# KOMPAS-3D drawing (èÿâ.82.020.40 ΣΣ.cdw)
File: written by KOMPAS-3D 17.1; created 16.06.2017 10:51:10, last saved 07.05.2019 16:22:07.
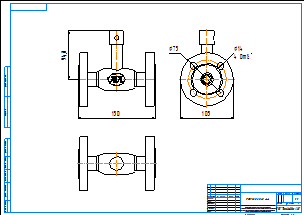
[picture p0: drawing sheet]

Sheet 1: A2, landscape

Title block, sheet 1: name: КШГ.82.020.40 фф; material: Внимание! Данный продукт является объектом авторского права ООО «Торговый Дом АДЛ». / Запрещается изменение, копирование, распространение / (в том числе путем копирования на другие сайты и ресурсы в Интернете) / или любое иное использование информации и объектов без предварительного / согласия правообладателя (ООО «Торговый Дом АДЛ»).; scale: 1:1; sheets: 1; organisation: ООО "Торговый дом АДЛ"; sheet format: A2; stored path: C:\Users\tra\Desktop\2д чертежи\Шаровые краны БИВАЛ\КШ_Бивал_серия_82_85\KOMPAS 2D\КШГ.82.020.40 фф.cdw

Views: Спереди 1, Проекционный вид 2, Проекционный вид 3
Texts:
  Klimkovich
  ADL
Dimensions and other numbers on the sheet: 150; 94,8; 75; 105; 14; 4 Отв.; 1:1; 1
